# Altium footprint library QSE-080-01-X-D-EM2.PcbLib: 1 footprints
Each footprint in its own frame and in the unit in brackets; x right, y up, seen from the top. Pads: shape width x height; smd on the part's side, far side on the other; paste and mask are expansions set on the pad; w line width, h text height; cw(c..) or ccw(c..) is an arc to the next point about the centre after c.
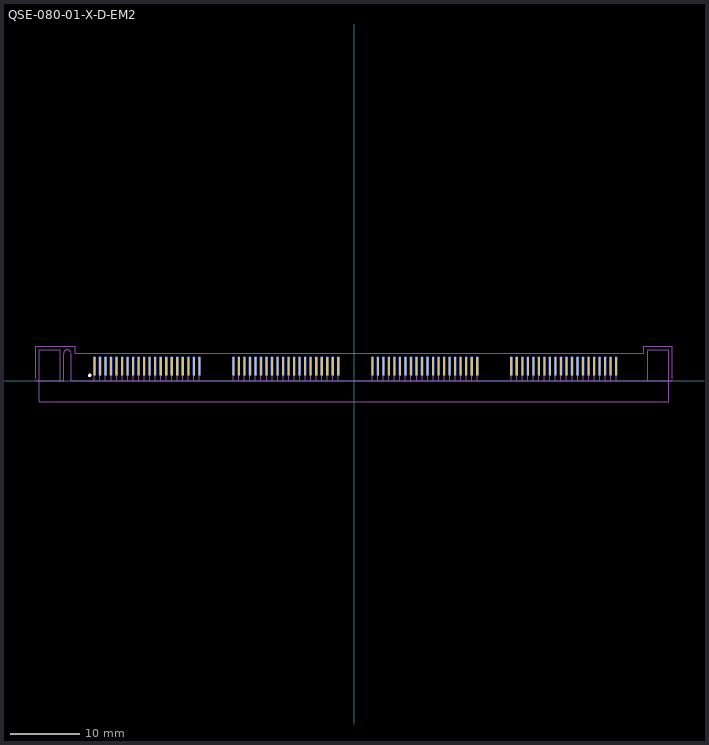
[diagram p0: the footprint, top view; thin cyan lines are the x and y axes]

## QSE-080-01-X-D-EM2 [mil] "0.80mm pitch, 160 pin, high speed socket; w/edge mounts"
height 142.91
pads (160):
  rect 12.01x105 smd far side mask+0: 1(-1480.49,82.5) 3(-1449,82.5) 5(-1417.5,82.5) 7(-1386,82.5) 9(-1354.51,82.5) 11(-1323.01,82.5) 13(-1291.52,82.5) 15(-1260.02,82.5) 17(-1228.52,82.5) 19(-1197.03,82.5) 21(-1165.53,82.5) 23(-1134.04,82.5) 25(-1102.54,82.5) 27(-1071.04,82.5) 29(-1039.55,82.5) 31(-1008.05,82.5) 33(-976.56,82.5) 35(-945.06,82.5) 37(-913.56,82.5) 39(-882.07,82.5) 42(-656.48,82.5) 44(-624.98,82.5) 46(-593.48,82.5) 48(-561.99,82.5) 50(-530.49,82.5) 52(-499,82.5) 54(-467.5,82.5) 56(-436,82.5) 58(-404.51,82.5) 60(-373.01,82.5) 62(-341.52,82.5) 64(-310.02,82.5) 66(-278.52,82.5) 68(-247.03,82.5) 70(-215.53,82.5) 72(-184.04,82.5) 74(-152.54,82.5) 76(-121.04,82.5) 78(-89.55,82.5) 80(-687.97,82.5) 82(136.04,82.5) 84(167.54,82.5) 86(199.04,82.5) 88(230.53,82.5) 90(262.03,82.5) 92(293.52,82.5) 94(325.02,82.5) 96(356.52,82.5) 98(388.01,82.5) 100(419.51,82.5) 102(451,82.5) 104(482.5,82.5) 106(514,82.5) 108(545.49,82.5) 110(576.99,82.5) 112(608.48,82.5) 114(639.98,82.5) 116(671.48,82.5) 118(702.97,82.5) 120(104.55,82.5) 122(928.56,82.5) 124(960.06,82.5) 126(991.56,82.5) 128(1023.05,82.5) 130(1054.55,82.5) 132(1086.04,82.5) 134(1117.54,82.5) 136(1149.04,82.5) 138(1180.53,82.5) 140(1212.03,82.5) 142(1243.52,82.5) 144(1275.02,82.5) 146(1306.52,82.5) 148(1338.01,82.5) 150(1369.51,82.5) 152(1401,82.5) 154(1432.5,82.5) 156(1464,82.5) 158(1495.49,82.5) 160(897.07,82.5)
  rect 12.01x105 smd mask+0: 2(-1480.49,82.5) 4(-1449,82.5) 6(-1417.5,82.5) 8(-1386,82.5) 10(-1354.51,82.5) 12(-1323.01,82.5) 14(-1291.52,82.5) 16(-1260.02,82.5) 18(-1228.52,82.5) 20(-1197.03,82.5) 22(-1165.53,82.5) 24(-1134.04,82.5) 26(-1102.54,82.5) 28(-1071.04,82.5) 30(-1039.55,82.5) 32(-1008.05,82.5) 34(-976.56,82.5) 36(-945.06,82.5) 38(-913.56,82.5) 40(-882.07,82.5) 41(-687.97,82.5) 43(-656.48,82.5) 45(-624.98,82.5) 47(-593.48,82.5) 49(-561.99,82.5) 51(-530.49,82.5) 53(-499,82.5) 55(-467.5,82.5) 57(-436,82.5) 59(-404.51,82.5) 61(-373.01,82.5) 63(-341.52,82.5) 65(-310.02,82.5) 67(-278.52,82.5) 69(-247.03,82.5) 71(-215.53,82.5) 73(-184.04,82.5) 75(-152.54,82.5) 77(-121.04,82.5) 79(-89.55,82.5) 81(104.55,82.5) 83(136.04,82.5) 85(167.54,82.5) 87(199.04,82.5) 89(230.53,82.5) 91(262.03,82.5) 93(293.52,82.5) 95(325.02,82.5) 97(356.52,82.5) 99(388.01,82.5) 101(419.51,82.5) 103(451,82.5) 105(482.5,82.5) 107(514,82.5) 109(545.49,82.5) 111(576.99,82.5) 113(608.48,82.5) 115(639.98,82.5) 117(671.48,82.5) 119(702.97,82.5) 121(897.07,82.5) 123(928.56,82.5) 125(960.06,82.5) 127(991.56,82.5) 129(1023.05,82.5) 131(1054.55,82.5) 133(1086.04,82.5) 135(1117.54,82.5) 137(1149.04,82.5) 139(1180.53,82.5) 141(1212.03,82.5) 143(1243.52,82.5) 145(1275.02,82.5) 147(1306.52,82.5) 149(1338.01,82.5) 151(1369.51,82.5) 153(1401,82.5) 155(1432.5,82.5) 157(1464,82.5) 159(1495.49,82.5)
Top Overlay:
  circle w9.84: c-1507.87,29.53 r4.92
Top Solder:
  lines w5: -1480.49,82.5 -1480.49,134.98 ; -1449,82.5 -1449,134.98 ; -1417.5,82.5 -1417.5,134.98 ; -1386,82.5 -1386,134.98 ; -1354.51,82.5 -1354.51,134.98 ; -1323.01,82.5 -1323.01,134.98 ; -1291.52,82.5 -1291.52,134.98 ; -1260.02,82.5 -1260.02,134.98 ; -1228.52,82.5 -1228.52,134.98 ; -1197.03,82.5 -1197.03,134.98 ; -1165.53,82.5 -1165.53,134.98 ; -1134.04,82.5 -1134.04,134.98 ; -1102.54,82.5 -1102.54,134.98 ; -1071.04,82.5 -1071.04,134.98 ; -1039.55,82.5 -1039.55,134.98 ; -1008.05,82.5 -1008.05,134.98 ; -976.56,82.5 -976.56,134.98 ; -945.06,82.5 -945.06,134.98 ; -913.56,82.5 -913.56,134.98 ; -882.07,82.5 -882.07,134.98 ; -687.97,82.5 -687.97,134.98 ; -656.48,82.5 -656.48,134.98 ; -624.98,82.5 -624.98,134.98 ; -593.48,82.5 -593.48,134.98 ; -561.99,82.5 -561.99,134.98 ; -530.49,82.5 -530.49,134.98 ; -499,82.5 -499,134.98 ; -467.5,82.5 -467.5,134.98 ; -436,82.5 -436,134.98 ; -404.51,82.5 -404.51,134.98 ; -373.01,82.5 -373.01,134.98 ; -341.52,82.5 -341.52,134.98 ; -310.02,82.5 -310.02,134.98 ; -278.52,82.5 -278.52,134.98 ; -247.03,82.5 -247.03,134.98 ; -215.53,82.5 -215.53,134.98 ; -184.04,82.5 -184.04,134.98 ; -152.54,82.5 -152.54,134.98 ; -121.04,82.5 -121.04,134.98 ; -89.55,82.5 -89.55,134.98 ; 104.55,82.5 104.55,134.98 ; 136.04,82.5 136.04,134.98 ; 167.54,82.5 167.54,134.98 ; 199.04,82.5 199.04,134.98 ; 230.53,82.5 230.53,134.98 ; 262.03,82.5 262.03,134.98 ; 293.52,82.5 293.52,134.98 ; 325.02,82.5 325.02,134.98 ; 356.52,82.5 356.52,134.98 ; 388.01,82.5 388.01,134.98 ; 419.51,82.5 419.51,134.98 ; 451,82.5 451,134.98 ; 482.5,82.5 482.5,134.98 ; 514,82.5 514,134.98 ; 545.49,82.5 545.49,134.98 ; 576.99,82.5 576.99,134.98 ; 608.48,82.5 608.48,134.98 ; 639.98,82.5 639.98,134.98 ; 671.48,82.5 671.48,134.98 ; 702.97,82.5 702.97,134.98 ; 897.07,82.5 897.07,134.98 ; 928.56,82.5 928.56,134.98 ; 960.06,82.5 960.06,134.98 ; 991.56,82.5 991.56,134.98 ; 1023.05,82.5 1023.05,134.98 ; 1054.55,82.5 1054.55,134.98 ; 1086.04,82.5 1086.04,134.98 ; 1117.54,82.5 1117.54,134.98 ; 1149.04,82.5 1149.04,134.98 ; 1180.53,82.5 1180.53,134.98 ; 1212.03,82.5 1212.03,134.98 ; 1243.52,82.5 1243.52,134.98 ; 1275.02,82.5 1275.02,134.98 ; 1306.52,82.5 1306.52,134.98 ; 1338.01,82.5 1338.01,134.98 ; 1369.51,82.5 1369.51,134.98 ; 1401,82.5 1401,134.98 ; 1432.5,82.5 1432.5,134.98 ; 1464,82.5 1464,134.98 ; 1495.49,82.5 1495.49,134.98
Bottom Solder:
  lines w5: -1480.49,82.5 -1480.49,134.98 ; -1449,82.5 -1449,134.98 ; -1417.5,82.5 -1417.5,134.98 ; -1386,82.5 -1386,134.98 ; -1354.51,82.5 -1354.51,134.98 ; -1323.01,82.5 -1323.01,134.98 ; -1291.52,82.5 -1291.52,134.98 ; -1260.02,82.5 -1260.02,134.98 ; -1228.52,82.5 -1228.52,134.98 ; -1197.03,82.5 -1197.03,134.98 ; -1165.53,82.5 -1165.53,134.98 ; -1134.04,82.5 -1134.04,134.98 ; -1102.54,82.5 -1102.54,134.98 ; -1071.04,82.5 -1071.04,134.98 ; -1039.55,82.5 -1039.55,134.98 ; -1008.05,82.5 -1008.05,134.98 ; -976.56,82.5 -976.56,134.98 ; -945.06,82.5 -945.06,134.98 ; -913.56,82.5 -913.56,134.98 ; -882.07,82.5 -882.07,134.98 ; -687.97,82.5 -687.97,134.98 ; -656.48,82.5 -656.48,134.98 ; -624.98,82.5 -624.98,134.98 ; -593.48,82.5 -593.48,134.98 ; -561.99,82.5 -561.99,134.98 ; -530.49,82.5 -530.49,134.98 ; -499,82.5 -499,134.98 ; -467.5,82.5 -467.5,134.98 ; -436,82.5 -436,134.98 ; -404.51,82.5 -404.51,134.98 ; -373.01,82.5 -373.01,134.98 ; -341.52,82.5 -341.52,134.98 ; -310.02,82.5 -310.02,134.98 ; -278.52,82.5 -278.52,134.98 ; -247.03,82.5 -247.03,134.98 ; -215.53,82.5 -215.53,134.98 ; -184.04,82.5 -184.04,134.98 ; -152.54,82.5 -152.54,134.98 ; -121.04,82.5 -121.04,134.98 ; -89.55,82.5 -89.55,134.98 ; 104.55,82.5 104.55,134.98 ; 136.04,82.5 136.04,134.98 ; 167.54,82.5 167.54,134.98 ; 199.04,82.5 199.04,134.98 ; 230.53,82.5 230.53,134.98 ; 262.03,82.5 262.03,134.98 ; 293.52,82.5 293.52,134.98 ; 325.02,82.5 325.02,134.98 ; 356.52,82.5 356.52,134.98 ; 388.01,82.5 388.01,134.98 ; 419.51,82.5 419.51,134.98 ; 451,82.5 451,134.98 ; 482.5,82.5 482.5,134.98 ; 514,82.5 514,134.98 ; 545.49,82.5 545.49,134.98 ; 576.99,82.5 576.99,134.98 ; 608.48,82.5 608.48,134.98 ; 639.98,82.5 639.98,134.98 ; 671.48,82.5 671.48,134.98 ; 702.97,82.5 702.97,134.98 ; 897.07,82.5 897.07,134.98 ; 928.56,82.5 928.56,134.98 ; 960.06,82.5 960.06,134.98 ; 991.56,82.5 991.56,134.98 ; 1023.05,82.5 1023.05,134.98 ; 1054.55,82.5 1054.55,134.98 ; 1086.04,82.5 1086.04,134.98 ; 1117.54,82.5 1117.54,134.98 ; 1149.04,82.5 1149.04,134.98 ; 1180.53,82.5 1180.53,134.98 ; 1212.03,82.5 1212.03,134.98 ; 1243.52,82.5 1243.52,134.98 ; 1275.02,82.5 1275.02,134.98 ; 1306.52,82.5 1306.52,134.98 ; 1338.01,82.5 1338.01,134.98 ; 1369.51,82.5 1369.51,134.98 ; 1401,82.5 1401,134.98 ; 1432.5,82.5 1432.5,134.98 ; 1464,82.5 1464,134.98 ; 1495.49,82.5 1495.49,134.98
Mechanical 12:
  lines w0.04: -1814.96,0 -1656.48,0 -1656.48,153.5 ; -1613.48,153.5 -1613.48,0 1814.96,0
Mechanical 13:
  circle w9.84: c-1507.87,29.53 r4.92
  lines w3.94: -1480.49,0 -1480.49,82.5 ; -1449,0 -1449,82.5 ; -1417.5,0 -1417.5,82.5 ; -1386,0 -1386,82.5 ; -1354.51,0 -1354.51,82.5 ; -1323.01,0 -1323.01,82.5 ; -1291.52,0 -1291.52,82.5 ; -1260.02,0 -1260.02,82.5 ; -1228.52,0 -1228.52,82.5 ; -1197.03,0 -1197.03,82.5 ; -1165.53,0 -1165.53,82.5 ; -1134.04,0 -1134.04,82.5 ; -1102.54,0 -1102.54,82.5 ; -1071.04,0 -1071.04,82.5 ; -1039.55,0 -1039.55,82.5 ; -1008.05,0 -1008.05,82.5 ; -976.56,0 -976.56,82.5 ; -945.06,0 -945.06,82.5 ; -913.56,0 -913.56,82.5 ; -882.07,0 -882.07,82.5 ; -687.97,0 -687.97,82.5 ; -656.48,0 -656.48,82.5 ; -624.98,0 -624.98,82.5 ; -593.48,0 -593.48,82.5 ; -561.99,0 -561.99,82.5 ; -530.49,0 -530.49,82.5 ; -499,0 -499,82.5 ; -467.5,0 -467.5,82.5 ; -436,0 -436,82.5 ; -404.51,0 -404.51,82.5 ; -373.01,0 -373.01,82.5 ; -341.52,0 -341.52,82.5 ; -310.02,0 -310.02,82.5 ; -278.52,0 -278.52,82.5 ; -247.03,0 -247.03,82.5 ; -215.53,0 -215.53,82.5 ; -184.04,0 -184.04,82.5 ; -152.54,0 -152.54,82.5 ; -121.04,0 -121.04,82.5 ; -89.55,0 -89.55,82.5 ; 104.55,0 104.55,82.5 ; 136.04,0 136.04,82.5 ; 167.54,0 167.54,82.5 ; 199.04,0 199.04,82.5 ; 230.53,0 230.53,82.5 ; 262.03,0 262.03,82.5 ; 293.52,0 293.52,82.5 ; 325.02,0 325.02,82.5 ; 356.52,0 356.52,82.5 ; 388.01,0 388.01,82.5 ; 419.51,0 419.51,82.5 ; 451,0 451,82.5 ; 482.5,0 482.5,82.5 ; 514,0 514,82.5 ; 545.49,0 545.49,82.5 ; 576.99,0 576.99,82.5 ; 608.48,0 608.48,82.5 ; 639.98,0 639.98,82.5 ; 671.48,0 671.48,82.5 ; 702.97,0 702.97,82.5 ; 897.07,0 897.07,82.5 ; 928.56,0 928.56,82.5 ; 960.06,0 960.06,82.5 ; 991.56,0 991.56,82.5 ; 1023.05,0 1023.05,82.5 ; 1054.55,0 1054.55,82.5 ; 1086.04,0 1086.04,82.5 ; 1117.54,0 1117.54,82.5 ; 1149.04,0 1149.04,82.5 ; 1180.53,0 1180.53,82.5 ; 1212.03,0 1212.03,82.5 ; 1243.52,0 1243.52,82.5 ; 1275.02,0 1275.02,82.5 ; 1306.52,0 1306.52,82.5 ; 1338.01,0 1338.01,82.5 ; 1369.51,0 1369.51,82.5 ; 1401,0 1401,82.5 ; 1432.5,0 1432.5,82.5 ; 1464,0 1464,82.5 ; 1495.49,0 1495.49,82.5 ; -1795.12,-120.08 -1795.12,175 -1675.12,175 -1675.12,0 -1656.48,0 -1656.48,153.5 cw(c-1634.98,153.5) -1613.48,153.5 -1613.48,0 1675.12,0 1675.12,175 1795.12,175 1795.12,-120.08 -1795.12,-120.08
  text ".Designator" at 0,0 h60
Mechanical 15:
  lines w1.97: -1814.96,9.84 -1814.96,194.88 -1590.55,194.88 -1590.55,155.51 1653.54,155.51 1653.54,194.88 1814.96,194.88 1814.96,9.84
Drill Drawing:
  lines w0.04: -1656.48,153.5 cw(c-1634.98,153.5) -1613.48,153.5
